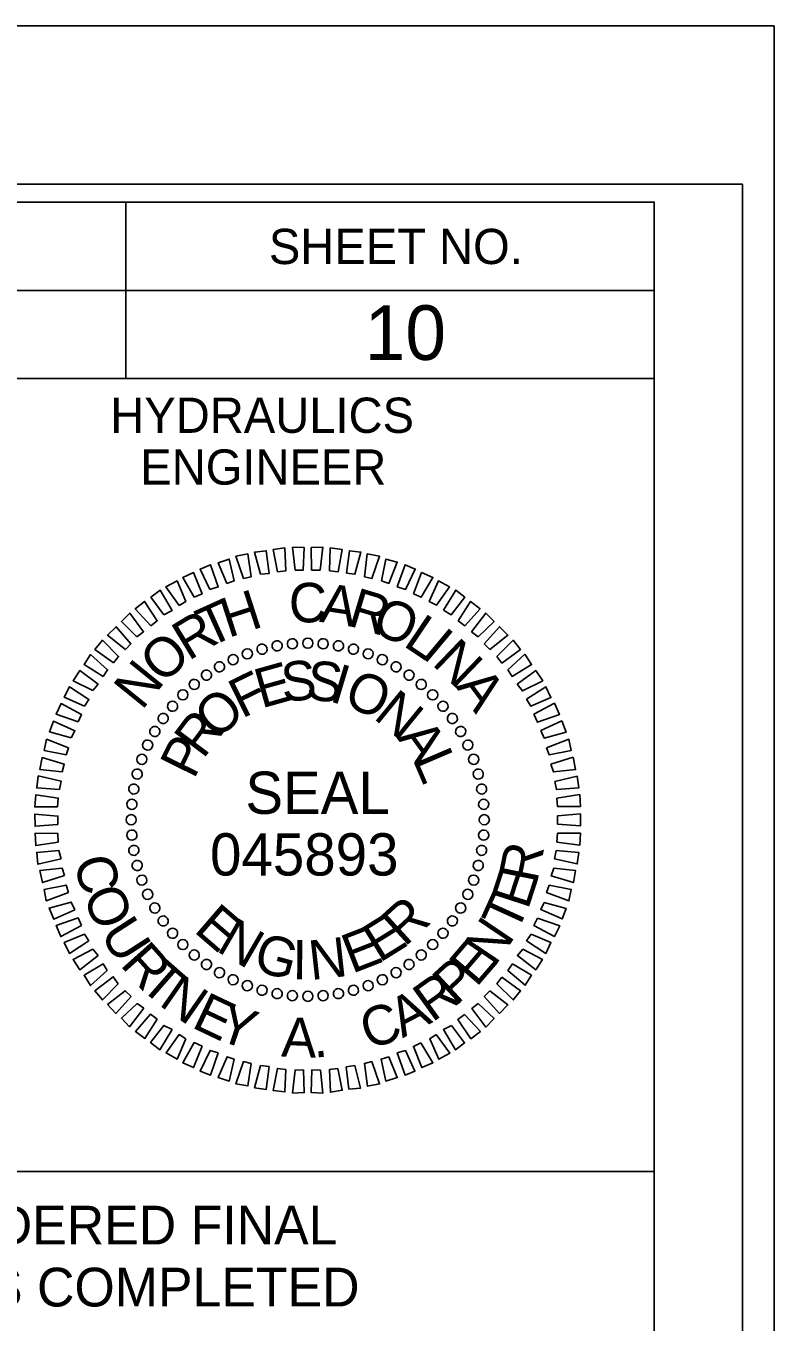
# Model space of a CAD drawing. Extents: x 1624665 to 1626605, y 896887 to 897987.
# Drawn here: x 1626243.2 to 1626349.4, y 897803.5 to 897987.4 of the extents above; entities that cross this region are included whole.
import ezdxf

# ---------------------------------------------------------------- set-up
doc = ezdxf.new("R2010")
doc.units = 0
for name, color, linetype in [('Default', 7, 'Continuous'), ('Sheet Cutting Line CELL', 7, 'Continuous'), ('Sheet Data Field CELL', 7, 'Continuous'), ('Sheet Plot Border Inside CELL', 7, 'Continuous'), ('Sheet Plot Border Outside CELL', 7, 'Continuous'), ('Sheet Profile CELL', 7, 'Continuous'), ('Sheet Profile Grid Major CELL', 7, 'Continuous'), ('Sheet Sticker Exception Certification CELL', 7, 'Continuous')]:
    doc.layers.add(name, color=color, linetype=linetype)

msp = doc.modelspace()

# ---------------------------------------------------------------- linework, layer by layer
at = {"layer": 'Default'}
for p, q in [((1626278.88, 897899.43), (1626278.88, 897899.43)), ((1626281.03, 897899.73), (1626281.03, 897899.73)), ((1626283.23, 897899.88), (1626283.23, 897899.88)), ((1626285.43, 897899.73), (1626285.43, 897899.73)), ((1626287.58, 897899.43), (1626287.58, 897899.43)), ((1626274.63, 897898.33), (1626274.63, 897898.33)), ((1626276.73, 897898.98), (1626276.73, 897898.98)), ((1626289.73, 897898.98), (1626289.73, 897898.98)), ((1626291.83, 897898.33), (1626291.83, 897898.33)), ((1626270.73, 897896.48), (1626270.73, 897896.48)), ((1626272.68, 897897.48), (1626272.68, 897897.48)), ((1626293.83, 897897.48), (1626293.83, 897897.48)), ((1626295.78, 897896.48), (1626295.78, 897896.48)), ((1626267.08, 897894.03), (1626267.08, 897894.03)), ((1626268.88, 897895.28), (1626268.88, 897895.28)), ((1626297.58, 897895.33), (1626297.58, 897895.33)), ((1626299.38, 897893.98), (1626299.38, 897893.98)), ((1626265.48, 897892.48), (1626265.48, 897892.48)), ((1626300.93, 897892.53), (1626300.93, 897892.53)), ((1626263.98, 897890.93), (1626263.98, 897890.93)), ((1626302.48, 897890.88), (1626302.48, 897890.88)), ((1626262.68, 897889.13), (1626262.68, 897889.13)), ((1626303.73, 897889.13), (1626303.73, 897889.13)), ((1626261.48, 897887.28), (1626261.48, 897887.28)), ((1626304.93, 897887.28), (1626304.93, 897887.28)), ((1626260.48, 897885.33), (1626260.48, 897885.33)), ((1626305.93, 897885.33), (1626305.93, 897885.33)), ((1626259.63, 897883.33), (1626259.63, 897883.33)), ((1626306.78, 897883.33), (1626306.78, 897883.33)), ((1626258.98, 897881.28), (1626258.98, 897881.28)), ((1626307.43, 897881.28), (1626307.43, 897881.28)), ((1626258.53, 897879.13), (1626258.53, 897879.13)), ((1626307.88, 897879.08), (1626307.88, 897879.08)), ((1626258.23, 897876.98), (1626258.23, 897876.98)), ((1626308.18, 897876.93), (1626308.18, 897876.93)), ((1626258.13, 897874.78), (1626258.13, 897874.78)), ((1626308.33, 897874.73), (1626308.33, 897874.73)), ((1626258.28, 897872.58), (1626258.28, 897872.58)), ((1626308.23, 897872.53), (1626308.23, 897872.53)), ((1626258.58, 897870.43), (1626258.58, 897870.43)), ((1626307.93, 897870.43), (1626307.93, 897870.43)), ((1626259.03, 897868.28), (1626259.03, 897868.28)), ((1626307.43, 897868.23), (1626307.43, 897868.23)), ((1626259.68, 897866.18), (1626259.68, 897866.18)), ((1626306.78, 897866.18), (1626306.78, 897866.18)), ((1626260.53, 897864.18), (1626260.53, 897864.18)), ((1626305.98, 897864.18), (1626305.98, 897864.18)), ((1626261.53, 897862.23), (1626261.53, 897862.23)), ((1626304.98, 897862.23), (1626304.98, 897862.23)), ((1626262.73, 897860.38), (1626262.73, 897860.38)), ((1626303.78, 897860.38), (1626303.78, 897860.38)), ((1626263.98, 897858.63), (1626263.98, 897858.63)), ((1626302.43, 897858.63), (1626302.43, 897858.63)), ((1626265.48, 897857.03), (1626265.48, 897857.03)), ((1626267.08, 897855.53), (1626267.08, 897855.53)), ((1626299.33, 897855.53), (1626299.33, 897855.53)), ((1626300.98, 897857.03), (1626300.98, 897857.03)), ((1626268.83, 897854.23), (1626268.83, 897854.23)), ((1626297.58, 897854.28), (1626297.58, 897854.28)), ((1626270.68, 897853.03), (1626270.68, 897853.03)), ((1626272.63, 897852.03), (1626272.63, 897852.03)), ((1626293.78, 897852.03), (1626293.78, 897852.03)), ((1626295.78, 897853.03), (1626295.78, 897853.03)), ((1626274.63, 897851.18), (1626274.63, 897851.18)), ((1626276.73, 897850.53), (1626276.73, 897850.53)), ((1626278.88, 897850.08), (1626278.88, 897850.08)), ((1626281.03, 897849.78), (1626281.03, 897849.78)), ((1626285.38, 897849.83), (1626285.38, 897849.83)), ((1626287.58, 897850.08), (1626287.58, 897850.08)), ((1626289.73, 897850.53), (1626289.73, 897850.53)), ((1626291.78, 897851.18), (1626291.78, 897851.18)), ((1626283.18, 897849.68), (1626283.18, 897849.68))]:
    msp.add_line(p, q, dxfattribs=at)
for points in [[(1626274.13, 897909.03), (1626273.03, 897912.18), (1626274.73, 897912.53), (1626275.18, 897909.28)], [(1626276.53, 897909.63), (1626275.68, 897912.78), (1626277.33, 897912.98), (1626277.73, 897909.73)], [(1626278.93, 897909.98), (1626278.33, 897913.13), (1626279.98, 897913.38), (1626280.13, 897910.13)], [(1626281.43, 897910.23), (1626281.08, 897913.48), (1626282.73, 897913.43), (1626282.58, 897910.23)], [(1626283.78, 897910.23), (1626283.73, 897913.43), (1626285.38, 897913.48), (1626284.98, 897910.23)], [(1626286.33, 897910.13), (1626286.43, 897913.38), (1626288.13, 897913.13), (1626287.53, 897909.98)], [(1626288.73, 897909.78), (1626289.13, 897912.98), (1626290.78, 897912.78), (1626289.93, 897909.63)], [(1626291.28, 897909.28), (1626291.68, 897912.53), (1626293.43, 897912.18), (1626292.33, 897909.03)], [(1626269.33, 897907.48), (1626267.98, 897910.38), (1626269.43, 897910.98), (1626270.53, 897907.83)], [(1626271.73, 897908.33), (1626270.53, 897911.28), (1626272.08, 897911.78), (1626272.78, 897908.68)], [(1626293.68, 897908.68), (1626294.33, 897911.78), (1626295.93, 897911.33), (1626294.73, 897908.33)], [(1626295.93, 897907.83), (1626297.03, 897910.98), (1626298.48, 897910.38), (1626297.08, 897907.48)], [(1626264.98, 897905.18), (1626263.08, 897907.83), (1626264.68, 897908.68), (1626265.93, 897905.78)], [(1626267.13, 897906.38), (1626265.48, 897909.18), (1626267.03, 897909.88), (1626268.23, 897906.88)], [(1626298.23, 897906.88), (1626299.38, 897909.88), (1626300.98, 897909.18), (1626299.33, 897906.38)], [(1626300.48, 897905.78), (1626301.78, 897908.68), (1626303.33, 897907.83), (1626301.48, 897905.23)], [(1626262.83, 897903.88), (1626260.98, 897906.38), (1626262.28, 897907.38), (1626263.98, 897904.48)], [(1626302.48, 897904.53), (1626304.23, 897907.38), (1626305.53, 897906.38), (1626303.58, 897903.88)], [(1626260.98, 897902.33), (1626258.73, 897904.73), (1626260.08, 897905.78), (1626261.88, 897903.03)], [(1626304.58, 897903.03), (1626306.33, 897905.78), (1626307.68, 897904.73), (1626305.53, 897902.33)], [(1626258.98, 897900.78), (1626256.78, 897902.93), (1626257.98, 897904.13), (1626259.93, 897901.48)], [(1626306.48, 897901.48), (1626308.48, 897904.13), (1626309.68, 897902.93), (1626307.43, 897900.78)], [(1626257.38, 897898.98), (1626254.83, 897900.98), (1626256.03, 897902.18), (1626258.13, 897899.78)], [(1626308.28, 897899.78), (1626310.43, 897902.18), (1626311.63, 897900.98), (1626309.08, 897898.98)], [(1626255.68, 897897.08), (1626253.03, 897898.98), (1626254.08, 897900.28), (1626256.38, 897897.98)], [(1626310.08, 897897.98), (1626312.38, 897900.28), (1626313.43, 897898.98), (1626310.78, 897897.03)], [(1626254.18, 897895.13), (1626251.48, 897896.83), (1626252.38, 897898.23), (1626254.83, 897896.08)], [(1626311.63, 897896.08), (1626314.03, 897898.28), (1626314.98, 897896.83), (1626312.23, 897895.13)], [(1626252.73, 897893.13), (1626249.93, 897894.53), (1626250.88, 897895.98), (1626253.48, 897894.03)], [(1626312.93, 897894.03), (1626315.58, 897895.98), (1626316.58, 897894.53), (1626313.68, 897893.08)], [(1626251.53, 897890.93), (1626248.68, 897892.18), (1626249.43, 897893.68), (1626252.18, 897891.88)], [(1626314.28, 897891.93), (1626317.03, 897893.68), (1626317.73, 897892.13), (1626314.88, 897890.93)], [(1626250.63, 897888.68), (1626247.53, 897889.78), (1626248.23, 897891.28), (1626251.13, 897889.73)], [(1626315.33, 897889.78), (1626318.23, 897891.33), (1626318.93, 897889.73), (1626315.83, 897888.63)], [(1626249.68, 897886.43), (1626246.58, 897887.28), (1626247.13, 897888.78), (1626250.18, 897887.43)], [(1626316.28, 897887.48), (1626319.28, 897888.83), (1626319.88, 897887.23), (1626316.78, 897886.38)], [(1626248.93, 897884.03), (1626245.83, 897884.63), (1626246.18, 897886.23), (1626249.28, 897885.03)], [(1626317.13, 897885.03), (1626320.28, 897886.23), (1626320.63, 897884.63), (1626317.48, 897884.03)], [(1626248.38, 897881.58), (1626245.23, 897881.93), (1626245.53, 897883.63), (1626248.68, 897882.68)], [(1626317.73, 897882.68), (1626320.88, 897883.68), (1626321.23, 897881.93), (1626318.08, 897881.58)], [(1626247.98, 897879.08), (1626244.78, 897879.33), (1626244.98, 897881.03), (1626248.23, 897880.28)], [(1626318.28, 897880.23), (1626321.48, 897880.98), (1626321.68, 897879.33), (1626318.53, 897879.08)], [(1626247.73, 897876.63), (1626244.48, 897876.63), (1626244.63, 897878.33), (1626247.83, 897877.88)], [(1626318.58, 897877.88), (1626321.83, 897878.38), (1626321.93, 897876.68), (1626318.68, 897876.68)], [(1626247.78, 897874.13), (1626244.53, 897873.88), (1626244.48, 897875.58), (1626247.78, 897875.33)], [(1626318.68, 897875.38), (1626321.93, 897875.63), (1626321.93, 897873.93), (1626318.68, 897874.18)], [(1626247.83, 897871.63), (1626244.63, 897871.13), (1626244.53, 897872.88), (1626247.78, 897872.83)], [(1626318.68, 897872.88), (1626321.93, 897872.88), (1626321.83, 897871.18), (1626318.58, 897871.63)], [(1626248.23, 897869.28), (1626244.93, 897868.48), (1626244.78, 897870.18), (1626247.93, 897870.43)], [(1626318.48, 897870.43), (1626321.68, 897870.18), (1626321.48, 897868.53), (1626318.23, 897869.28)], [(1626248.73, 897866.88), (1626245.58, 897865.88), (1626245.23, 897867.58), (1626248.38, 897867.93)], [(1626318.13, 897867.93), (1626321.23, 897867.58), (1626320.93, 897865.88), (1626317.78, 897866.83)], [(1626249.28, 897864.48), (1626246.13, 897863.28), (1626245.83, 897864.93), (1626248.93, 897865.53)], [(1626317.48, 897865.53), (1626320.63, 897864.93), (1626320.28, 897863.28), (1626317.13, 897864.48)], [(1626250.18, 897862.03), (1626247.18, 897860.68), (1626246.53, 897862.28), (1626249.68, 897863.13)], [(1626316.78, 897863.08), (1626319.88, 897862.23), (1626319.33, 897860.73), (1626316.28, 897862.08)], [(1626251.13, 897859.78), (1626248.18, 897858.23), (1626247.53, 897859.78), (1626250.63, 897860.88)], [(1626315.83, 897860.83), (1626318.98, 897859.73), (1626318.23, 897858.23), (1626315.33, 897859.78)], [(1626252.18, 897857.63), (1626249.43, 897855.83), (1626248.68, 897857.38), (1626251.53, 897858.58)], [(1626314.93, 897858.58), (1626317.73, 897857.38), (1626317.03, 897855.83), (1626314.28, 897857.63)], [(1626253.48, 897855.53), (1626250.88, 897853.53), (1626249.93, 897854.98), (1626252.73, 897856.43)], [(1626313.73, 897856.43), (1626316.53, 897854.98), (1626315.58, 897853.53), (1626312.98, 897855.53)], [(1626254.78, 897853.43), (1626252.38, 897851.28), (1626251.48, 897852.73), (1626254.18, 897854.38)], [(1626312.28, 897854.38), (1626314.98, 897852.73), (1626314.08, 897851.33), (1626311.63, 897853.43)], [(1626256.33, 897851.53), (1626254.08, 897849.23), (1626253.03, 897850.53), (1626255.63, 897852.53)], [(1626310.78, 897852.48), (1626313.43, 897850.53), (1626312.38, 897849.23), (1626310.08, 897851.53)], [(1626258.18, 897849.73), (1626255.98, 897847.33), (1626254.83, 897848.58), (1626257.33, 897850.53)], [(1626309.08, 897850.53), (1626311.63, 897848.53), (1626310.43, 897847.33), (1626308.28, 897849.73)], [(1626259.98, 897848.08), (1626257.93, 897845.43), (1626256.78, 897846.63), (1626259.03, 897848.73)], [(1626307.43, 897848.73), (1626309.68, 897846.58), (1626308.48, 897845.38), (1626306.53, 897848.03)], [(1626261.88, 897846.53), (1626260.13, 897843.78), (1626258.78, 897844.78), (1626260.93, 897847.23)], [(1626305.48, 897847.18), (1626307.73, 897844.78), (1626306.38, 897843.73), (1626304.53, 897846.48)], [(1626263.98, 897845.03), (1626262.23, 897842.18), (1626260.93, 897843.18), (1626262.83, 897845.63)], [(1626265.93, 897843.73), (1626264.68, 897840.83), (1626263.13, 897841.73), (1626264.98, 897844.33)], [(1626301.43, 897844.33), (1626303.38, 897841.68), (1626301.83, 897840.83), (1626300.53, 897843.73)], [(1626303.63, 897845.63), (1626305.48, 897843.13), (1626304.18, 897842.18), (1626302.48, 897845.03)], [(1626268.23, 897842.68), (1626267.03, 897839.63), (1626265.48, 897840.33), (1626267.13, 897843.18)], [(1626299.28, 897843.13), (1626300.98, 897840.33), (1626299.43, 897839.63), (1626298.23, 897842.63)], [(1626270.53, 897841.73), (1626269.43, 897838.58), (1626267.98, 897839.13), (1626269.38, 897842.08)], [(1626272.78, 897840.83), (1626272.08, 897837.73), (1626270.53, 897838.23), (1626271.78, 897841.18)], [(1626294.73, 897841.18), (1626295.93, 897838.23), (1626294.33, 897837.73), (1626293.63, 897840.83)], [(1626297.08, 897842.08), (1626298.43, 897839.13), (1626297.03, 897838.58), (1626295.93, 897841.73)], [(1626275.18, 897840.23), (1626274.73, 897837.03), (1626273.03, 897837.33), (1626274.13, 897840.48)], [(1626277.73, 897839.78), (1626277.33, 897836.53), (1626275.68, 897836.78), (1626276.53, 897839.93)], [(1626280.13, 897839.38), (1626279.98, 897836.18), (1626278.33, 897836.38), (1626278.93, 897839.53)], [(1626282.63, 897839.33), (1626282.73, 897836.08), (1626281.08, 897836.03), (1626281.43, 897839.28)], [(1626285.03, 897839.28), (1626285.38, 897836.03), (1626283.73, 897836.08), (1626283.83, 897839.33)], [(1626287.48, 897839.53), (1626288.13, 897836.43), (1626286.48, 897836.13), (1626286.33, 897839.38)], [(1626289.93, 897839.93), (1626290.73, 897836.73), (1626289.08, 897836.58), (1626288.68, 897839.73)], [(1626292.33, 897840.48), (1626293.43, 897837.33), (1626291.73, 897836.98), (1626291.28, 897840.23)]]:
    msp.add_lwpolyline(points, close=True, dxfattribs=at)
for centre, major_axis in [((1626276.74, 897899.01), (-0.186, 0.695)), ((1626278.88, 897899.48), (-0.125, 0.708)), ((1626281.05, 897899.77), (-0.063, 0.717)), ((1626283.23, 897899.86), (0, 0.719)), ((1626285.41, 897899.77), (0.063, 0.717)), ((1626287.58, 897899.48), (0.125, 0.708)), ((1626289.71, 897899.01), (0.186, 0.695)), ((1626272.64, 897897.51), (-0.304, 0.652)), ((1626274.66, 897898.35), (-0.246, 0.676)), ((1626291.8, 897898.35), (0.246, 0.676)), ((1626293.82, 897897.51), (0.304, 0.652)), ((1626268.86, 897895.33), (-0.413, 0.589)), ((1626270.7, 897896.51), (-0.36, 0.623)), ((1626295.76, 897896.51), (0.36, 0.623)), ((1626297.6, 897895.33), (0.413, 0.589)), ((1626267.12, 897894), (-0.462, 0.551)), ((1626299.33, 897894), (0.462, 0.551)), ((1626265.51, 897892.52), (-0.509, 0.509)), ((1626300.95, 897892.52), (0.509, 0.509)), ((1626264.04, 897890.91), (-0.551, 0.462)), ((1626302.42, 897890.91), (0.551, 0.462)), ((1626262.71, 897889.18), (-0.589, 0.413)), ((1626303.75, 897889.18), (0.589, 0.413)), ((1626261.53, 897887.33), (-0.623, 0.36)), ((1626304.93, 897887.33), (0.623, 0.36)), ((1626260.52, 897885.4), (-0.652, 0.304)), ((1626305.94, 897885.4), (0.652, 0.304)), ((1626259.69, 897883.38), (-0.676, 0.246)), ((1626306.77, 897883.38), (0.676, 0.246)), ((1626259.03, 897881.29), (-0.695, 0.186)), ((1626307.43, 897881.29), (0.695, 0.186)), ((1626258.55, 897879.16), (-0.708, 0.125)), ((1626307.9, 897879.16), (0.708, 0.125)), ((1626258.27, 897876.99), (-0.717, 0.063)), ((1626308.19, 897876.99), (0.717, 0.063)), ((1626258.17, 897874.81), (-0.719, 0)), ((1626308.28, 897874.81), (0.719, 0)), ((1626258.27, 897872.62), (-0.717, -0.063)), ((1626308.19, 897872.62), (0.717, -0.063)), ((1626258.55, 897870.46), (-0.708, -0.125)), ((1626307.9, 897870.46), (0.708, -0.125)), ((1626259.03, 897868.32), (-0.695, -0.186)), ((1626307.43, 897868.32), (0.695, -0.186)), ((1626259.69, 897866.24), (-0.676, -0.246)), ((1626306.77, 897866.24), (0.676, -0.246)), ((1626260.52, 897864.22), (-0.652, -0.304)), ((1626305.94, 897864.22), (0.652, -0.304)), ((1626261.53, 897862.28), (-0.623, -0.36)), ((1626304.93, 897862.28), (0.623, -0.36)), ((1626262.71, 897860.44), (-0.589, -0.413)), ((1626303.75, 897860.44), (0.589, -0.413)), ((1626264.04, 897858.7), (-0.551, -0.462)), ((1626302.42, 897858.7), (0.551, -0.462)), ((1626265.51, 897857.09), (-0.509, -0.509)), ((1626300.95, 897857.09), (0.509, -0.509)), ((1626267.12, 897855.61), (-0.462, -0.551)), ((1626299.33, 897855.61), (0.462, -0.551)), ((1626268.86, 897854.28), (-0.413, -0.589)), ((1626270.7, 897853.11), (-0.36, -0.623)), ((1626295.76, 897853.11), (0.36, -0.623)), ((1626297.6, 897854.28), (0.413, -0.589)), ((1626272.64, 897852.1), (-0.304, -0.652)), ((1626274.66, 897851.26), (-0.246, -0.676)), ((1626291.8, 897851.26), (0.246, -0.676)), ((1626293.82, 897852.1), (0.304, -0.652)), ((1626276.74, 897850.61), (-0.186, -0.695)), ((1626278.88, 897850.13), (-0.125, -0.708)), ((1626281.05, 897849.85), (-0.063, -0.717)), ((1626283.23, 897849.75), (0, -0.719)), ((1626285.41, 897849.85), (0.063, -0.717)), ((1626287.58, 897850.13), (0.125, -0.708)), ((1626289.71, 897850.61), (0.186, -0.695))]:
    msp.add_ellipse(centre, major_axis=major_axis, ratio=0.999708, dxfattribs=at)
at = {"layer": 'Sheet Cutting Line CELL'}
msp.add_line((1626349.4, 897987.44), (1624665.4, 897987.44), dxfattribs=at)
at = {"layer": 'Sheet Plot Border Inside CELL'}
msp.add_lwpolyline([(1624678.4, 896909.89), (1626344.9, 896909.89), (1626344.9, 897964.99), (1624678.4, 897964.99)], close=True, dxfattribs=at)
at = {"layer": 'Sheet Plot Border Outside CELL'}
msp.add_lwpolyline([(1624665.4, 896887.44), (1626349.4, 896887.44), (1626349.4, 897987.44), (1624665.4, 897987.44)], close=True, dxfattribs=at)
at = {"layer": 'Sheet Profile CELL'}
for p, q in [((1626257.4, 897962.39), (1626257.4, 897937.39)), ((1626132.35, 897949.89), (1626332.4, 897949.89))]:
    msp.add_line(p, q, dxfattribs=at)
for points in [[(1626332.4, 897962.44), (1624832.4, 897962.44), (1624832.4, 896912.44), (1626332.4, 896912.44)], [(1626132.35, 897962.44), (1626332.4, 897962.44), (1626332.4, 897937.39), (1626132.35, 897937.39)], [(1626232.4, 897937.39), (1626332.4, 897937.39), (1626332.4, 897824.89), (1626232.4, 897824.89)]]:
    msp.add_lwpolyline(points, close=True, dxfattribs=at)
at = {"layer": 'Sheet Profile Grid Major CELL'}
msp.add_lwpolyline([(1626282.4, 897801.39), (1626282.4, 897462.44), (1626332.4, 897462.44), (1626332.4, 897812.44)], dxfattribs=at)
at = {"layer": 'Sheet Sticker Exception Certification CELL'}
for p, q in [((1626132.35, 897824.89), (1626332.39, 897824.89)), ((1626132.35, 897824.89), (1626332.39, 897824.89)), ((1626332.39, 897824.88), (1626332.39, 897801.38)), ((1626332.39, 897824.88), (1626332.39, 897801.38))]:
    msp.add_line(p, q, dxfattribs=at)

# ---------------------------------------------------------------- texts
at = {"layer": 'Default'}
for s, height, rotation, p in [('H', 5.6, 17.9268, (1626271.95, 897900.59)), ('C', 5.6, 359.8514, (1626280.53, 897902.82)), ('A', 5.6, 351.2223, (1626284.77, 897902.91)), ('R', 5.6, 343.1874, (1626288.69, 897902.43)), ('T', 5.6, 24.3275, (1626269.14, 897899.17)), ('O', 5.6, 336.242, (1626292, 897901.57)), ('R', 5.6, 31.2729, (1626266.3, 897897.28)), ('L', 5.6, 326.0282, (1626296.61, 897899.59)), ('I', 5.6, 320.0485, (1626299.13, 897898.07)), ('O', 5.6, 41.4867, (1626262.57, 897893.92)), ('N', 5.6, 316.0496, (1626300.71, 897896.9)), ('N', 5.6, 51.032, (1626259.68, 897890.22)), ('F', 5.6, 26.1465, (1626273.88, 897889.11)), ('E', 5.6, 15.6529, (1626276.65, 897890.58)), ('S', 5.6, 5.0487, (1626279.68, 897891.52)), ('S', 5.6, 354.1866, (1626282.9, 897891.9)), ('I', 5.6, 343.3245, (1626286.14, 897891.66)), ('O', 5.6, 336.6634, (1626288.08, 897891.21)), ('A', 5.6, 306.5043, (1626304.14, 897893.7)), ('O', 5.6, 42.0574, (1626270.31, 897885.99)), ('N', 5.6, 320.7526, (1626292.4, 897889.26)), ('R', 5.6, 53.1038, (1626268.39, 897883.3)), ('P', 5.6, 63.7079, (1626267.08, 897880.42)), ('A', 5.6, 305.8367, (1626295.83, 897886.42)), ('L', 5.6, 293.1688, (1626298.08, 897883.38)), ('SEAL', 5.992, 360, (1626274.38, 897875.64)), ('045893', 5.994, 360, (1626269.36, 897866.89)), ('R', 5.6, 78.5969, (1626315.75, 897865.62)), ('C', 5.6, 284.0401, (1626249.99, 897869.05)), ('E', 5.6, 71.9487, (1626314.47, 897861.92)), ('O', 5.6, 292.6692, (1626251.22, 897864.12)), ('T', 5.6, 65.548, (1626312.85, 897858.52)), ('E', 5.6, 319.2324, (1626266.91, 897859)), ('R', 5.6, 42.4535, (1626296.98, 897856.66)), ('U', 5.6, 302.883, (1626253.62, 897858.61)), ('N', 5.6, 329.8366, (1626270.09, 897856.26)), ('E', 5.6, 31.8494, (1626293.41, 897854.44)), ('N', 5.6, 56.0027, (1626309.74, 897853.84)), ('E', 5.6, 21.2452, (1626289.5, 897852.92)), ('R', 5.6, 311.7969, (1626256.48, 897854.21)), ('G', 5.6, 344.7525, (1626275.29, 897853.49)), ('I', 5.6, 359.6683, (1626281.03, 897852.15)), ('N', 5.6, 6.3293, (1626283.67, 897852.05)), ('E', 5.6, 49.3544, (1626307.14, 897850.91)), ('T', 5.6, 318.7423, (1626259.16, 897851.13)), ('P', 5.6, 42.7062, (1626304.22, 897848.3)), ('N', 5.6, 325.143, (1626261.94, 897848.59)), ('R', 5.6, 35.7608, (1626300.87, 897845.96)), ('E', 5.6, 334.6883, (1626266.58, 897845.41)), ('A', 5.6, 27.7259, (1626296.67, 897843.78)), ('Y', 5.6, 341.3366, (1626270.09, 897843.68)), ('C', 5.6, 19.0968, (1626291.87, 897842.12)), ('A', 5.6, 357.753, (1626279.41, 897841.22)), ('.', 5.6, 5.7878, (1626284.13, 897841.02))]:
    msp.add_text(s, height=height, rotation=rotation, dxfattribs=at).set_placement(p)
at = {"layer": 'Sheet Data Field CELL'}
msp.add_text('10', height=7.75, dxfattribs=at).set_placement((1626291.32, 897940.05))
at = {"layer": 'Sheet Profile CELL'}
for s, p in [('SHEET NO.', (1626277.71, 897953.65)), ('HYDRAULICS', (1626255.21, 897929.7)), ('ENGINEER', (1626259.46, 897922.35))]:
    msp.add_text(s, height=5, dxfattribs=at).set_placement(p)
at = {"layer": 'Sheet Sticker Exception Certification CELL'}
for s, p in [('DOCUMENT NOT CONSIDERED FINAL', (1626153.42, 897814.54)), ('DOCUMENT NOT CONSIDERED FINAL', (1626153.42, 897814.54)), ('UNLESS ALL SIGNATURES COMPLETED', (1626148.35, 897805.74)), ('UNLESS ALL SIGNATURES COMPLETED', (1626148.35, 897805.74))]:
    msp.add_text(s, height=5.5, dxfattribs=at).set_placement(p)

doc.saveas('drawing.dxf')
